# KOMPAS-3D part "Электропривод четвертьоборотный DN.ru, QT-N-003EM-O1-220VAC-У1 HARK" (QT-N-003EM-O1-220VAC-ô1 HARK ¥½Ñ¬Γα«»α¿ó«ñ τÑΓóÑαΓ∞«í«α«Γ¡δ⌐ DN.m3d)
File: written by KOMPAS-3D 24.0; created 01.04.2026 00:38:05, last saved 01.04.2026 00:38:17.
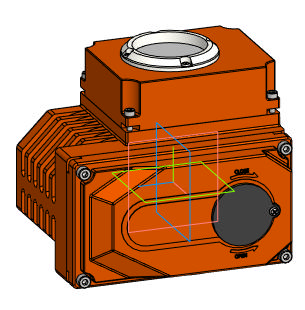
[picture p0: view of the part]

Document properties: Автор: DN.RU; Полное имя файла: D:\PROJECT CAD\DN.RU\...195\Исходники\220В\QT-N-003EM-O1-220VAC-У1 HARK Электропривод четвертьоборотный DN.ru\QT-N-003EM-O1-220VAC-У1 HARK Электропривод четвертьоборотный DN.m3d

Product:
- Body: Твердое тело1  | qty 1
    Масса: 8.093373
- Part/product: Электропривод четвертьоборотный DN.ru  | designation QT-N-003EM-O1-220VAC-У1 HARK
    Масса: 2.1
    Раздел спецификации: Прочие изделия
    Комментарий: D300-05869
    Примечание: D300-08218
    additional columns: Типовые

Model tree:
1. Твердое тело1  (labels: Твердое тело1)

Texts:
  QT-N-003EM-O1-220VAC-У1 HARK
